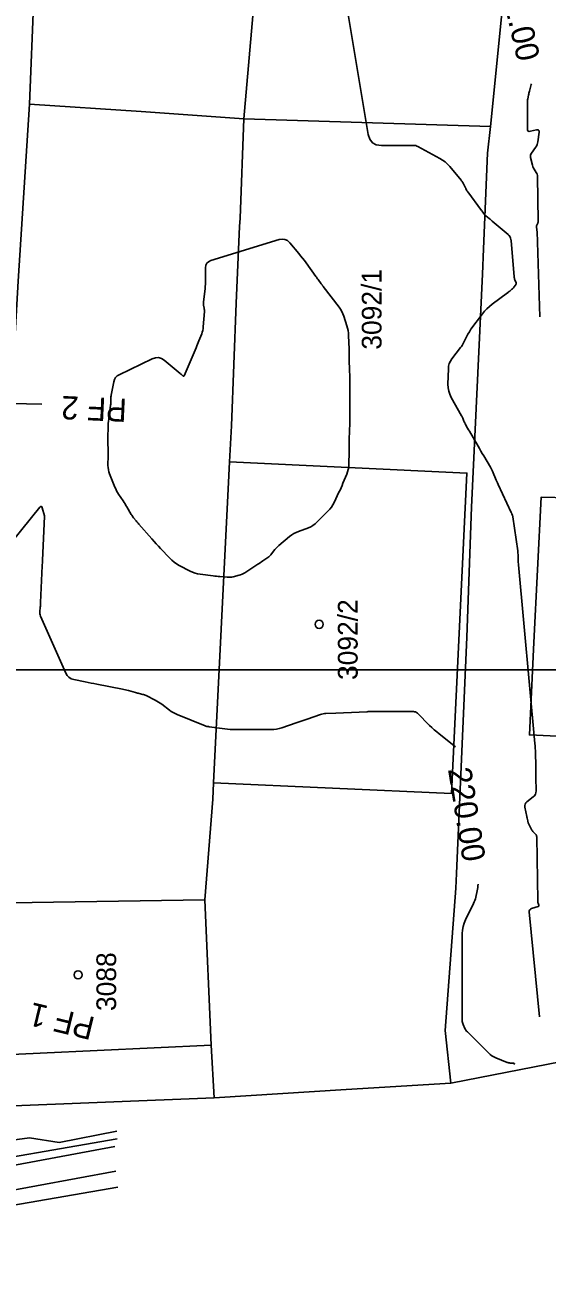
# Model space of a CAD drawing. Extents: x -534410 to -534262, y -1190162 to -1189584.
# Drawn here: x -534318.6 to -534296.1, y -1190135.2 to -1190081.7 of the extents above; entities that cross this region are included whole.
import ezdxf

# ---------------------------------------------------------------- set-up
doc = ezdxf.new("R2010")
doc.units = 0
for name, color, linetype in [('14', 7, 'Continuous'), ('30', 7, 'Continuous'), ('31', 7, 'Continuous'), ('40', 7, 'Continuous'), ('_N_text', 7, 'Continuous'), ('_rámeček', 7, 'Continuous'), ('_tenka', 7, 'Continuous'), ('Hranice parcel', 7, 'Continuous'), ('Parcelní čísla', 7, 'Continuous'), ('Polygon budovy', 7, 'Continuous'), ('Vrstva 1', 7, 'Continuous'), ('Vrstva 2', 7, 'Continuous'), ('Značky budov', 7, 'Continuous')]:
    doc.layers.add(name, color=color, linetype=linetype)

msp = doc.modelspace()

# ---------------------------------------------------------------- linework, layer by layer
at = {"layer": '14'}
msp.add_lwpolyline([(-534314.619, -1190129.669), (-534321.91, -1190130.93), (-534322.66, -1190131.1), (-534328.55, -1190132.02), (-534329.42, -1190132.15), (-534330.73, -1190132.71), (-534340.6, -1190136.91), (-534340.966, -1190136.972)], dxfattribs=at)
at = {"layer": '30'}
for points in [[(-534296.764, -1190084.214), (-534296.774, -1190084.248), (-534296.847, -1190084.535), (-534296.857, -1190084.576), (-534296.867, -1190084.618), (-534296.876, -1190084.66), (-534296.884, -1190084.701), (-534296.918, -1190084.869), (-534296.925, -1190084.911), (-534296.931, -1190084.953), (-534296.934, -1190084.995), (-534296.935, -1190085.038), (-534296.935, -1190085.639), (-534296.935, -1190085.655), (-534296.934, -1190085.672), (-534296.933, -1190085.712), (-534296.933, -1190085.729), (-534296.933, -1190085.737), (-534296.933, -1190086.16), (-534296.925, -1190086.216), (-534296.901, -1190086.252), (-534296.86, -1190086.267), (-534296.804, -1190086.262), (-534296.545, -1190086.202), (-534296.49, -1190086.197), (-534296.453, -1190086.212), (-534296.434, -1190086.247), (-534296.434, -1190086.303), (-534296.487, -1190086.71), (-534296.499, -1190086.776), (-534296.52, -1190086.839), (-534296.548, -1190086.898), (-534296.583, -1190086.955), (-534296.758, -1190087.201), (-534296.783, -1190087.246), (-534296.798, -1190087.292), (-534296.802, -1190087.341), (-534296.795, -1190087.391), (-534296.717, -1190087.725), (-534296.705, -1190087.774), (-534296.702, -1190087.786), (-534296.698, -1190087.797), (-534296.693, -1190087.809), (-534296.687, -1190087.819), (-534296.553, -1190088.035), (-534296.531, -1190088.075), (-534296.516, -1190088.117), (-534296.506, -1190088.161), (-534296.502, -1190088.207), (-534296.469, -1190090.14), (-534296.47, -1190090.162), (-534296.473, -1190090.182), (-534296.479, -1190090.203), (-534296.487, -1190090.223), (-534296.543, -1190090.337), (-534296.543, -1190090.34), (-534296.543, -1190090.343), (-534296.541, -1190090.352), (-534296.541, -1190090.355), (-534296.525, -1190090.537), (-534296.524, -1190090.541), (-534296.524, -1190090.545), (-534296.523, -1190090.548), (-534296.521, -1190090.552), (-534296.516, -1190090.566), (-534296.515, -1190090.57), (-534296.514, -1190090.574), (-534296.513, -1190090.577), (-534296.513, -1190090.581), (-534296.398, -1190094.261)], [(-534319.995, -1190104.97), (-534317.954, -1190102.463), (-534317.919, -1190102.43), (-534317.889, -1190102.423), (-534317.865, -1190102.441), (-534317.847, -1190102.486), (-534317.753, -1190102.832), (-534317.751, -1190102.844), (-534317.751, -1190102.846), (-534317.751, -1190102.854), (-534317.831, -1190104.733), (-534317.832, -1190104.756), (-534317.832, -1190104.778), (-534317.833, -1190104.822), (-534317.833, -1190104.833), (-534317.834, -1190104.844), (-534317.835, -1190104.855), (-534317.837, -1190104.866), (-534317.846, -1190104.925), (-534317.848, -1190104.938), (-534317.849, -1190104.952), (-534317.851, -1190104.965), (-534317.851, -1190104.979), (-534317.918, -1190106.568), (-534317.92, -1190106.617), (-534317.923, -1190106.666), (-534317.926, -1190106.715), (-534317.93, -1190106.763), (-534317.947, -1190106.959), (-534317.948, -1190107.007), (-534317.943, -1190107.054), (-534317.932, -1190107.1), (-534317.915, -1190107.146), (-534316.832, -1190109.601), (-534316.772, -1190109.705), (-534316.694, -1190109.787), (-534316.598, -1190109.846), (-534316.483, -1190109.883), (-534315.99, -1190109.985), (-534315.866, -1190110.01), (-534315.743, -1190110.035), (-534315.619, -1190110.06), (-534315.496, -1190110.084), (-534314.392, -1190110.301), (-534314.327, -1190110.314), (-534314.261, -1190110.329), (-534314.196, -1190110.344), (-534314.132, -1190110.361), (-534313.819, -1190110.444), (-534313.781, -1190110.454), (-534313.743, -1190110.463), (-534313.705, -1190110.473), (-534313.667, -1190110.482), (-534313.513, -1190110.52), (-534313.475, -1190110.53), (-534313.438, -1190110.542), (-534313.402, -1190110.557), (-534313.366, -1190110.574), (-534312.979, -1190110.768), (-534312.904, -1190110.808), (-534312.831, -1190110.851), (-534312.76, -1190110.898), (-534312.692, -1190110.948), (-534312.367, -1190111.197), (-534312.288, -1190111.253), (-534312.207, -1190111.304), (-534312.122, -1190111.348), (-534312.034, -1190111.388), (-534310.821, -1190111.883), (-534310.807, -1190111.888), (-534310.793, -1190111.893), (-534310.778, -1190111.896), (-534310.764, -1190111.899), (-534310.705, -1190111.907), (-534310.676, -1190111.912), (-534310.647, -1190111.916), (-534309.976, -1190112.005), (-534309.86, -1190112.018), (-534309.743, -1190112.028), (-534309.625, -1190112.034), (-534309.508, -1190112.036), (-534307.978, -1190112.036), (-534307.861, -1190112.031), (-534307.746, -1190112.017), (-534307.633, -1190111.993), (-534307.521, -1190111.96), (-534306.898, -1190111.747), (-534306.77, -1190111.703), (-534306.514, -1190111.616), (-534306.429, -1190111.587), (-534305.858, -1190111.392), (-534305.8, -1190111.374), (-534305.742, -1190111.361), (-534305.682, -1190111.352), (-534305.622, -1190111.347), (-534305.196, -1190111.328), (-534304.18, -1190111.282), (-534303.847, -1190111.267), (-534303.795, -1190111.265), (-534303.743, -1190111.263), (-534303.691, -1190111.262), (-534303.639, -1190111.262), (-534301.847, -1190111.262), (-534301.797, -1190111.267), (-534301.751, -1190111.28), (-534301.708, -1190111.304), (-534301.669, -1190111.336), (-534301.151, -1190111.856), (-534301.05, -1190111.954), (-534300.948, -1190112.048), (-534300.842, -1190112.139), (-534300.733, -1190112.228), (-534300.028, -1190112.782)], [(-534299.062, -1190118.704), (-534299.064, -1190118.773), (-534299.07, -1190118.844), (-534299.08, -1190118.914), (-534299.094, -1190118.983), (-534299.157, -1190119.261), (-534299.174, -1190119.329), (-534299.196, -1190119.396), (-534299.222, -1190119.462), (-534299.252, -1190119.527), (-534299.604, -1190120.238), (-534299.665, -1190120.379), (-534299.708, -1190120.525), (-534299.734, -1190120.675), (-534299.743, -1190120.829), (-534299.743, -1190124.571), (-534299.741, -1190124.616), (-534299.733, -1190124.661), (-534299.721, -1190124.705), (-534299.704, -1190124.747), (-534299.627, -1190124.915), (-534299.606, -1190124.956), (-534299.582, -1190124.995), (-534299.554, -1190125.031), (-534299.523, -1190125.065), (-534298.617, -1190125.971), (-534298.544, -1190126.036), (-534298.466, -1190126.094), (-534298.383, -1190126.143), (-534298.294, -1190126.183), (-534297.808, -1190126.376), (-534297.775, -1190126.387), (-534297.742, -1190126.396), (-534297.708, -1190126.402), (-534297.673, -1190126.405), (-534297.533, -1190126.413), (-534297.505, -1190126.418), (-534297.492, -1190126.428), (-534297.495, -1190126.444), (-534297.512, -1190126.467)]]:
    msp.add_lwpolyline(points, dxfattribs=at)
at = {"layer": '31'}
msp.add_lwpolyline([(-534305.286, -1190077.421), (-534303.794, -1190086.394), (-534303.729, -1190086.603), (-534303.613, -1190086.753), (-534303.446, -1190086.843), (-534303.229, -1190086.873), (-534301.779, -1190086.873), (-534301.772, -1190086.873), (-534301.764, -1190086.871), (-534301.75, -1190086.868), (-534301.747, -1190086.868), (-534301.743, -1190086.868), (-534301.74, -1190086.869), (-534301.737, -1190086.871), (-534301.696, -1190086.898), (-534301.688, -1190086.903), (-534301.68, -1190086.907), (-534301.672, -1190086.912), (-534301.663, -1190086.917), (-534300.707, -1190087.429), (-534300.587, -1190087.5), (-534300.477, -1190087.582), (-534300.374, -1190087.674), (-534300.28, -1190087.777), (-534299.793, -1190088.363), (-534299.769, -1190088.394), (-534299.747, -1190088.426), (-534299.726, -1190088.459), (-534299.707, -1190088.492), (-534299.617, -1190088.664), (-534299.608, -1190088.682), (-534299.599, -1190088.7), (-534299.59, -1190088.718), (-534299.581, -1190088.736), (-534299.547, -1190088.808), (-534299.538, -1190088.826), (-534299.528, -1190088.843), (-534299.517, -1190088.86), (-534299.505, -1190088.876), (-534298.906, -1190089.672), (-534298.891, -1190089.692), (-534298.877, -1190089.711), (-534298.863, -1190089.731), (-534298.849, -1190089.75), (-534298.795, -1190089.829), (-534298.78, -1190089.848), (-534298.765, -1190089.866), (-534298.748, -1190089.883), (-534298.73, -1190089.899), (-534298.576, -1190090.024), (-534298.544, -1190090.05), (-534298.512, -1190090.076), (-534298.481, -1190090.102), (-534298.45, -1190090.129), (-534297.769, -1190090.706), (-534297.757, -1190090.718), (-534297.745, -1190090.73), (-534297.734, -1190090.744), (-534297.724, -1190090.758), (-534297.681, -1190090.823), (-534297.675, -1190090.834), (-534297.669, -1190090.845), (-534297.664, -1190090.857), (-534297.661, -1190090.87), (-534297.648, -1190090.92), (-534297.645, -1190090.933), (-534297.643, -1190090.946), (-534297.641, -1190090.959), (-534297.64, -1190090.972), (-534297.503, -1190092.533), (-534297.499, -1190092.565), (-534297.493, -1190092.597), (-534297.484, -1190092.629), (-534297.474, -1190092.66), (-534297.425, -1190092.788), (-534297.418, -1190092.816), (-534297.418, -1190092.842), (-534297.426, -1190092.867), (-534297.441, -1190092.891), (-534297.518, -1190092.984), (-534297.538, -1190093.007), (-534297.559, -1190093.029), (-534297.581, -1190093.049), (-534297.603, -1190093.069), (-534297.697, -1190093.146), (-534297.72, -1190093.165), (-534297.744, -1190093.184), (-534297.767, -1190093.202), (-534297.792, -1190093.221), (-534298.457, -1190093.716), (-534298.572, -1190093.808), (-534298.68, -1190093.908), (-534298.78, -1190094.015), (-534298.872, -1190094.13), (-534299.366, -1190094.794), (-534299.384, -1190094.82), (-534299.401, -1190094.846), (-534299.418, -1190094.872), (-534299.433, -1190094.899), (-534299.495, -1190095.008), (-534299.51, -1190095.035), (-534299.525, -1190095.063), (-534299.539, -1190095.09), (-534299.554, -1190095.118), (-534299.689, -1190095.382), (-534299.717, -1190095.435), (-534299.748, -1190095.486), (-534299.781, -1190095.535), (-534299.816, -1190095.583), (-534300.187, -1190096.061), (-534300.253, -1190096.16), (-534300.3, -1190096.265), (-534300.329, -1190096.376), (-534300.341, -1190096.494), (-534300.357, -1190097.162), (-534300.351, -1190097.312), (-534300.325, -1190097.456), (-534300.28, -1190097.595), (-534300.215, -1190097.73), (-534299.77, -1190098.518), (-534299.757, -1190098.542), (-534299.745, -1190098.566), (-534299.734, -1190098.59), (-534299.723, -1190098.615), (-534299.671, -1190098.745), (-534299.663, -1190098.765), (-534299.655, -1190098.785), (-534299.637, -1190098.825), (-534299.633, -1190098.834), (-534299.628, -1190098.844), (-534299.623, -1190098.854), (-534299.618, -1190098.863), (-534299.509, -1190099.05), (-534299.469, -1190099.119), (-534299.429, -1190099.188), (-534299.054, -1190099.835), (-534298.995, -1190099.936), (-534298.936, -1190100.037), (-534298.877, -1190100.138), (-534298.817, -1190100.239), (-534298.529, -1190100.727), (-534298.495, -1190100.786), (-534298.463, -1190100.847), (-534298.434, -1190100.908), (-534298.407, -1190100.971), (-534298.302, -1190101.224), (-534298.276, -1190101.288), (-534298.248, -1190101.35), (-534298.22, -1190101.413), (-534298.192, -1190101.475), (-534297.629, -1190102.685), (-534297.622, -1190102.7), (-534297.615, -1190102.716), (-534297.609, -1190102.732), (-534297.603, -1190102.748), (-534297.579, -1190102.812), (-534297.574, -1190102.829), (-534297.569, -1190102.845), (-534297.565, -1190102.862), (-534297.563, -1190102.878), (-534297.352, -1190104.338), (-534297.345, -1190104.389), (-534297.34, -1190104.439), (-534297.337, -1190104.489), (-534297.335, -1190104.54), (-534297.331, -1190104.743), (-534297.329, -1190104.794), (-534297.327, -1190104.844), (-534297.323, -1190104.895), (-534297.319, -1190104.946), (-534296.61, -1190112.638), (-534296.602, -1190112.741), (-534296.595, -1190112.845), (-534296.59, -1190112.948), (-534296.586, -1190113.052), (-534296.574, -1190113.588), (-534296.573, -1190113.631), (-534296.573, -1190113.674), (-534296.572, -1190113.716), (-534296.572, -1190113.759), (-534296.572, -1190113.93), (-534296.572, -1190113.973), (-534296.572, -1190114.015), (-534296.571, -1190114.058), (-534296.57, -1190114.101), (-534296.557, -1190114.683), (-534296.564, -1190114.76), (-534296.587, -1190114.828), (-534296.627, -1190114.889), (-534296.683, -1190114.942), (-534296.957, -1190115.15), (-534297.004, -1190115.196), (-534297.035, -1190115.25), (-534297.047, -1190115.309), (-534297.042, -1190115.376), (-534296.959, -1190115.784), (-534296.955, -1190115.805), (-534296.948, -1190115.837), (-534296.946, -1190115.848), (-534296.922, -1190115.967), (-534296.918, -1190115.988), (-534296.911, -1190116.009), (-534296.904, -1190116.03), (-534296.895, -1190116.05), (-534296.755, -1190116.345), (-534296.739, -1190116.375), (-534296.721, -1190116.403), (-534296.7, -1190116.429), (-534296.677, -1190116.453), (-534296.581, -1190116.547), (-534296.559, -1190116.572), (-534296.544, -1190116.6), (-534296.535, -1190116.63), (-534296.531, -1190116.662), (-534296.489, -1190119.423), (-534296.488, -1190119.447), (-534296.485, -1190119.47), (-534296.481, -1190119.493), (-534296.474, -1190119.515), (-534296.446, -1190119.606), (-534296.443, -1190119.626), (-534296.447, -1190119.643), (-534296.458, -1190119.656), (-534296.477, -1190119.664), (-534296.756, -1190119.75), (-534296.802, -1190119.771), (-534296.834, -1190119.802), (-534296.851, -1190119.844), (-534296.853, -1190119.895), (-534296.414, -1190124.407)], dxfattribs=at)
msp.add_lwpolyline([(-534307.508, -1190090.906), (-534307.388, -1190090.921), (-534307.278, -1190090.973), (-534307.179, -1190091.064), (-534306.792, -1190091.521), (-534306.708, -1190091.622), (-534306.625, -1190091.726), (-534306.545, -1190091.831), (-534306.467, -1190091.937), (-534306.052, -1190092.517), (-534306.028, -1190092.55), (-534306.005, -1190092.583), (-534305.981, -1190092.615), (-534305.957, -1190092.648), (-534305.82, -1190092.835), (-534305.809, -1190092.849), (-534305.786, -1190092.879), (-534305.774, -1190092.893), (-534305.753, -1190092.919), (-534305.743, -1190092.931), (-534305.734, -1190092.943), (-534305.046, -1190093.842), (-534304.984, -1190093.931), (-534304.93, -1190094.024), (-534304.884, -1190094.121), (-534304.847, -1190094.222), (-534304.714, -1190094.637), (-534304.684, -1190094.741), (-534304.662, -1190094.847), (-534304.647, -1190094.954), (-534304.64, -1190095.062), (-534304.62, -1190095.656), (-534304.619, -1190095.688), (-534304.618, -1190095.719), (-534304.618, -1190095.75), (-534304.617, -1190095.782), (-534304.617, -1190095.907), (-534304.617, -1190095.939), (-534304.617, -1190095.97), (-534304.616, -1190096.001), (-534304.615, -1190096.033), (-534304.596, -1190096.626), (-534304.593, -1190096.735), (-534304.591, -1190096.845), (-534304.59, -1190096.954), (-534304.589, -1190097.063), (-534304.589, -1190098.627), (-534304.59, -1190098.736), (-534304.591, -1190098.844), (-534304.592, -1190098.953), (-534304.595, -1190099.062), (-534304.61, -1190099.647), (-534304.61, -1190099.68), (-534304.611, -1190099.713), (-534304.611, -1190099.746), (-534304.611, -1190099.779), (-534304.611, -1190099.91), (-534304.611, -1190099.943), (-534304.612, -1190099.976), (-534304.612, -1190100.009), (-534304.613, -1190100.042), (-534304.629, -1190100.633), (-534304.636, -1190100.738), (-534304.654, -1190100.84), (-534304.681, -1190100.941), (-534304.717, -1190101.039), (-534304.883, -1190101.428), (-534304.925, -1190101.525), (-534304.967, -1190101.621), (-534305.011, -1190101.717), (-534305.056, -1190101.813), (-534305.267, -1190102.257), (-534305.321, -1190102.36), (-534305.384, -1190102.457), (-534305.454, -1190102.549), (-534305.533, -1190102.634), (-534306.005, -1190103.106), (-534306.088, -1190103.181), (-534306.177, -1190103.245), (-534306.273, -1190103.3), (-534306.375, -1190103.344), (-534306.797, -1190103.501), (-534306.901, -1190103.544), (-534306.999, -1190103.595), (-534307.093, -1190103.655), (-534307.182, -1190103.722), (-534307.652, -1190104.11), (-534307.696, -1190104.149), (-534307.738, -1190104.19), (-534307.777, -1190104.233), (-534307.814, -1190104.279), (-534307.957, -1190104.466), (-534307.994, -1190104.511), (-534308.034, -1190104.553), (-534308.078, -1190104.591), (-534308.125, -1190104.626), (-534308.338, -1190104.773), (-534308.39, -1190104.809), (-534308.442, -1190104.844), (-534308.494, -1190104.879), (-534308.546, -1190104.913), (-534309.116, -1190105.287), (-534309.173, -1190105.321), (-534309.232, -1190105.35), (-534309.293, -1190105.374), (-534309.356, -1190105.392), (-534309.614, -1190105.456), (-534309.679, -1190105.469), (-534309.744, -1190105.477), (-534309.809, -1190105.479), (-534309.875, -1190105.476), (-534310.185, -1190105.448), (-534310.259, -1190105.441), (-534310.333, -1190105.433), (-534310.406, -1190105.425), (-534310.48, -1190105.417), (-534311.032, -1190105.35), (-534311.147, -1190105.331), (-534311.259, -1190105.302), (-534311.368, -1190105.263), (-534311.473, -1190105.213), (-534311.948, -1190104.964), (-534312.058, -1190104.9), (-534312.162, -1190104.827), (-534312.259, -1190104.746), (-534312.35, -1190104.657), (-534312.743, -1190104.237), (-534312.837, -1190104.135), (-534312.931, -1190104.033), (-534313.024, -1190103.93), (-534313.116, -1190103.826), (-534313.685, -1190103.182), (-534313.714, -1190103.149), (-534313.742, -1190103.116), (-534313.77, -1190103.082), (-534313.798, -1190103.048), (-534313.908, -1190102.912), (-534313.935, -1190102.878), (-534313.96, -1190102.843), (-534313.984, -1190102.806), (-534314.007, -1190102.769), (-534314.197, -1190102.446), (-534314.236, -1190102.38), (-534314.277, -1190102.314), (-534314.318, -1190102.249), (-534314.36, -1190102.184), (-534314.555, -1190101.89), (-534314.6, -1190101.819), (-534314.641, -1190101.746), (-534314.678, -1190101.67), (-534314.712, -1190101.593), (-534314.945, -1190101.016), (-534314.975, -1190100.93), (-534314.996, -1190100.841), (-534315.008, -1190100.751), (-534315.011, -1190100.659), (-534315.004, -1190100.237), (-534315.003, -1190100.17), (-534315.003, -1190100.103), (-534315.004, -1190100.036), (-534315.006, -1190099.969), (-534315.016, -1190099.701), (-534315.017, -1190099.634), (-534315.018, -1190099.567), (-534315.019, -1190099.5), (-534315.018, -1190099.433), (-534315.01, -1190099.025), (-534315.007, -1190098.935), (-534315.001, -1190098.845), (-534314.992, -1190098.755), (-534314.981, -1190098.666), (-534314.896, -1190098.059), (-534314.892, -1190098.023), (-534314.889, -1190097.988), (-534314.887, -1190097.952), (-534314.886, -1190097.916), (-534314.886, -1190097.773), (-534314.885, -1190097.737), (-534314.883, -1190097.702), (-534314.879, -1190097.666), (-534314.873, -1190097.631), (-534314.761, -1190097.059), (-534314.731, -1190096.959), (-534314.681, -1190096.874), (-534314.612, -1190096.804), (-534314.523, -1190096.749), (-534313.108, -1190096.064), (-534312.97, -1190096.017), (-534312.837, -1190096.012), (-534312.709, -1190096.049), (-534312.586, -1190096.127), (-534311.896, -1190096.697), (-534311.88, -1190096.71), (-534311.865, -1190096.724), (-534311.849, -1190096.737), (-534311.834, -1190096.751), (-534311.773, -1190096.806), (-534311.759, -1190096.816), (-534311.747, -1190096.818), (-534311.736, -1190096.811), (-534311.727, -1190096.796), (-534311.211, -1190095.586), (-534311.18, -1190095.512), (-534311.15, -1190095.439), (-534311.12, -1190095.365), (-534311.09, -1190095.29), (-534310.973, -1190094.993), (-534310.947, -1190094.918), (-534310.927, -1190094.842), (-534310.912, -1190094.764), (-534310.904, -1190094.685), (-534310.858, -1190094.024), (-534310.857, -1190093.989), (-534310.858, -1190093.955), (-534310.861, -1190093.92), (-534310.867, -1190093.886), (-534310.894, -1190093.749), (-534310.899, -1190093.715), (-534310.901, -1190093.68), (-534310.901, -1190093.646), (-534310.898, -1190093.611), (-534310.829, -1190093.054), (-534310.817, -1190092.949), (-534310.809, -1190092.844), (-534310.804, -1190092.739), (-534310.803, -1190092.634), (-534310.803, -1190092.139), (-534310.789, -1190092.032), (-534310.746, -1190091.945), (-534310.676, -1190091.88), (-534310.578, -1190091.835), (-534307.64, -1190090.929)], close=True, dxfattribs=at)
at = {"layer": '_N_text'}
msp.add_lwpolyline([(-534317.865, -1190098.015), (-534329.862, -1190097.767)], dxfattribs=at)
at = {"layer": '_rámeček'}
msp.add_lwpolyline([(-534410.126, -1190004.47), (-534261.626, -1190004.47), (-534261.626, -1190109.47), (-534410.126, -1190109.47)], close=True, dxfattribs=at)
at = {"layer": '_tenka'}
for p, q in [((-534340.286, -1190134.762), (-534314.711, -1190130.002)), ((-534340.592, -1190135.853), (-534314.669, -1190131.063))]:
    msp.add_line(p, q, dxfattribs=at)
at = {"layer": 'Hranice parcel'}
for p, q in [((-534318.39, -1190085.1), (-534317.63, -1190065.52)), ((-534309.15, -1190085.72), (-534307.92, -1190071.47)), ((-534298.53, -1190086.06), (-534297.88, -1190079.61)), ((-534309.15, -1190085.72), (-534298.53, -1190086.06)), ((-534300.24, -1190127.27), (-534285.05, -1190124.32)), ((-534320.3, -1190128.29), (-534310.43, -1190127.9))]:
    msp.add_line(p, q, dxfattribs=at)
for points in [[(-534320.3, -1190128.29), (-534320.41, -1190126.09), (-534320.16, -1190119.52), (-534319.24, -1190099.01), (-534318.88, -1190092.72), (-534318.39, -1190085.1)], [(-534309.15, -1190085.72), (-534313.58, -1190085.41), (-534318.39, -1190085.1)], [(-534309.77, -1190100.51), (-534309.69, -1190098.95), (-534309.48, -1190093.67), (-534309.34, -1190090.37), (-534309.32, -1190090), (-534309.15, -1190085.72)], [(-534298.53, -1190086.06), (-534298.65, -1190087.21), (-534298.82, -1190091.33), (-534298.87, -1190092.42), (-534299.34, -1190102.45), (-534299.54, -1190108.06), (-534299.99, -1190118.24), (-534300.02, -1190118.87), (-534300.48, -1190125), (-534300.24, -1190127.27)], [(-534310.46, -1190114.33), (-534309.8, -1190101.09), (-534309.77, -1190100.51)], [(-534309.77, -1190100.51), (-534299.54, -1190100.99), (-534300.2, -1190114.79), (-534310.46, -1190114.33)], [(-534310.43, -1190127.9), (-534310.57, -1190125.63), (-534310.83, -1190119.37), (-534310.49, -1190115.03), (-534310.46, -1190114.33)], [(-534300.24, -1190127.27), (-534304.74, -1190127.55), (-534310.43, -1190127.9)]]:
    msp.add_lwpolyline(points, dxfattribs=at)
at = {"layer": 'Polygon budovy'}
for points in [[(-534300.2, -1190114.79), (-534299.54, -1190100.99), (-534309.77, -1190100.51), (-534309.8, -1190101.09), (-534310.46, -1190114.33)], [(-534284.38, -1190112.87), (-534283.82, -1190102.63), (-534283.82, -1190102.51), (-534293.24, -1190102.14), (-534293.19, -1190100.76), (-534295.09, -1190100.69), (-534295.15, -1190102.06), (-534296.34, -1190102.02), (-534296.65, -1190108.29), (-534296.85, -1190112.27)], [(-534310.83, -1190119.37), (-534320.16, -1190119.52), (-534320.41, -1190126.09), (-534310.57, -1190125.63)]]:
    msp.add_lwpolyline(points, close=True, dxfattribs=at)
at = {"layer": 'Vrstva 1'}
msp.add_lwpolyline([(-534331.19, -1190131.62), (-534329.547, -1190131.285), (-534327.31, -1190130.83), (-534324.28, -1190130.41), (-534321.532, -1190130.045), (-534318.4, -1190129.63), (-534317.12, -1190129.83), (-534314.625, -1190129.337)], dxfattribs=at)
at = {"layer": 'Vrstva 2'}
msp.add_lwpolyline([(-534340.731, -1190136.249), (-534320.329, -1190132.749), (-534314.58, -1190131.758)], dxfattribs=at)
at = {"layer": 'Značky budov'}
for centre in [(-534305.908, -1190107.504), (-534316.299, -1190122.604)]:
    msp.add_circle(centre, 0.175, dxfattribs=at)

# ---------------------------------------------------------------- texts
at = {"layer": '40'}
for s, rotation, p in [('221.00', 282.8374, (-534298.262, -1190079.322)), ('220.00', 279.1123, (-534300.361, -1190113.745))]:
    msp.add_text(s, height=1, rotation=rotation, dxfattribs=at).set_placement(p)
at = {"layer": '_N_text'}
for s, rotation, p in [('PF 2', 177.4128, (-534314.177, -1190097.789)), ('PF 1', 166.3357, (-534315.518, -1190124.452))]:
    msp.add_text(s, height=1, rotation=rotation, dxfattribs=at).set_placement(p)
at = {"layer": 'Parcelní čísla'}
for s, p in [('3092/1', (-534303.221, -1190095.672)), ('3092/2', (-534304.251, -1190109.902)), ('3088', (-534314.66, -1190124.163))]:
    msp.add_text(s, height=0.85, rotation=90, dxfattribs=at).set_placement(p)

doc.saveas('drawing.dxf')
